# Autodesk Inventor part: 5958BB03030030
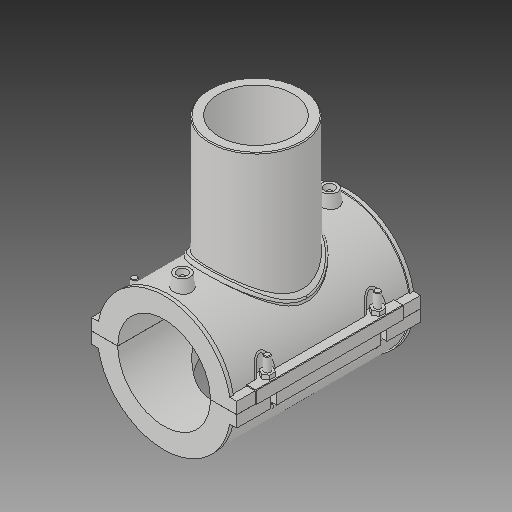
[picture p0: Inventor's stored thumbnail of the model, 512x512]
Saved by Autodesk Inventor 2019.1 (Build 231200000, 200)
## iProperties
Created: 2017-07
Part Number: 5958BB03030030
Material: Generic
Description: PLASSON BRANCH SADDLE 3'' x 3''
Document SubType Name: Modeling
Designer: KIM
Mass: 764.267 g
Surface Area: 1930.38 cm^2
Volume: 764.267 cm^3
Density: 1 g/cm^3
Appearance: Default
Author: KIM
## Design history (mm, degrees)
derived "5958B.ipt"
feature "Solid1::5958B.ipt"
feature "Solid2::5958B.ipt"
feature "Solid3::5958B.ipt"
tag "TaggingFeature1"
body "Solid1"
body "Solid2"
body "Solid3"
other parameters: "d0" = 88.7, "d2" = 139.192, "d3" = 22.175, "d4" = 176.022, "d5" = 0, "d6" = 0.1, "d8" = 0, "d19" = 6, "d20" = 6, "d21" = 105.6132, "d23" = 0, "d24" = 52.8066, "d26" = 0, "d27" = 3, "d28" = 3, "d29" = 3, "d30" = 29.56667, "d31" = 6, "d32" = 0, "d33" = 0, "d34" = 0.6, "d40" = 65.14352, "d41" = 97.57, "d43" = 0, "d45" = 0, "d47" = 169.572, "d48" = 88.7, "d50" = 0, "d70" = 15, "d72" = 0, "d73" = 6, "d75" = 5, "d76" = 0, "d77" = 4.435, "d78" = 74.35, "d79" = 15, "d80" = 70.4088, "d82" = 5 deg, "d84" = 4, "d85" = 14, "d86" = 0, "d87" = 3, "d88" = 0, "d89" = 1, "d90" = 1, "d91" = 140.8176, "d92" = 0, "d93" = 0.5, "d94" = 46.68421, "d96" = 127.78152, "d97" = 3.52044, "d98" = 0, "d102" = 2.661, "d103" = 70.96, "d105" = 0, "d109" = -35.64467, "d117" = 0.887, "d120" = 140 deg, "d121" = 24.228, "d122" = 20 deg, "d123" = 250.552, "d124" = 75.1656, "d126" = 0, "d143" = 93.135, "d150" = 15.966, "d159" = 7.3152, "d161" = 2.2175, "d162" = 105.6132, "d163" = 0, "d167" = 17.74, "d168" = 56.94364, "d173" = 1, "d175" = 44.35, "d176" = 20 deg, "d177" = 6.209, "d178" = 36.576, "d180" = 0, "d185" = 57.20715, "d186" = 57.20715, "d187" = 62.638, "d188" = 10.9728, "d189" = 6.209, "d190" = 0, "d191" = 93.957, "d200" = 18.288, "d202" = 0, "d216" = 158.4198, "d217" = 0, "d221" = 65.12814, "d222" = 6.209, "d223" = 3.7254, "d224" = 44.35, "d225" = 3.7254, "d227" = 12.7728, "d230" = 54.994, "d236" = 11.5 deg, "d238" = 20 deg, "d239" = 6.209, "d240" = 0, "d241" = 0, "d242" = 6.2484, "d_" = 88.7, "B_" = 139.192, "H_" = 106.934, "L_" = 176.022, "d_t" = 6, "d_1" = 88.7, "H_1" = 88.646, "d1" = 125.276, "d148" = 2.2175, "d160" = 2.2175
